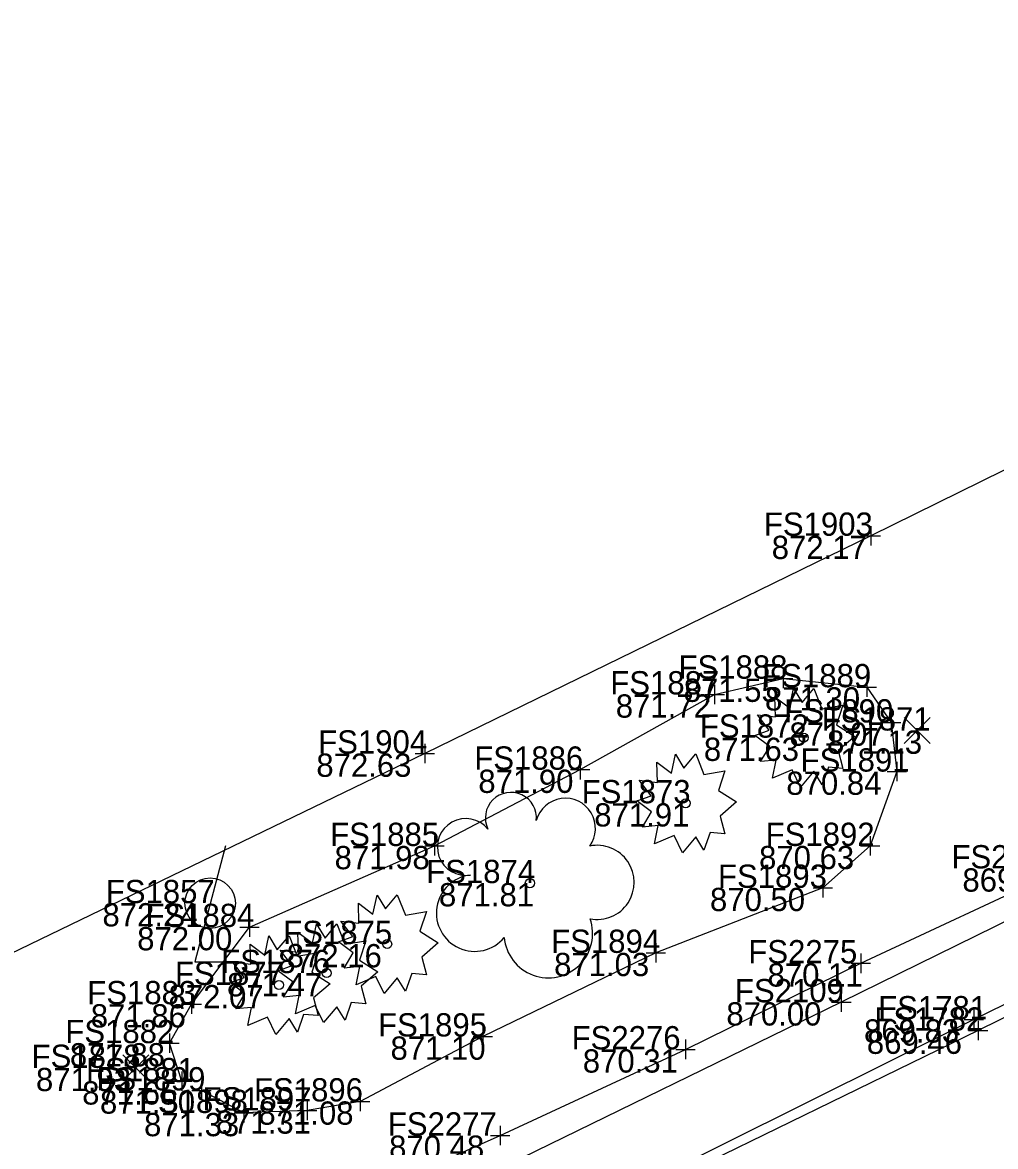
# Model space of a CAD drawing. Extents: x 1479420 to 1479833, y 379731 to 380103.
# Drawn here: x 1479688.8 to 1479739, y 379970.7 to 380028.7 of the extents above; entities that cross this region are included whole.
import ezdxf

# ---------------------------------------------------------------- set-up
doc = ezdxf.new("R2010")
doc.units = 0
for name, color, linetype in [('LT_X_Poles', 7, 'Continuous'), ('PV_X_Curb', 7, 'Continuous'), ('PV_X_Walk', 7, 'Continuous'), ('SV_X_Random_Point', 7, 'Continuous'), ('SV_X_Shot_Marker', 7, 'Continuous'), ('SV_X_Text_Elevation', 7, 'Continuous'), ('SV_X_Text_Name', 7, 'Continuous'), ('UT_X_Gas', 7, 'Continuous'), ('VG_X_Cells', 7, 'Continuous'), ('VG_X_Flower_Bed', 7, 'Continuous')]:
    doc.layers.add(name, color=color, linetype=linetype)

msp = doc.modelspace()

# ---------------------------------------------------------------- linework, layer by layer
at = {"layer": 'LT_X_Poles'}
msp.add_lwpolyline([(1479699.283, 379986.176), (1479697.708, 379980.191), (1479700.071, 379980.191)], dxfattribs=at)
msp.add_circle((1479698.496, 379983.222), 1.3, dxfattribs=at)
at = {"layer": 'PV_X_Curb'}
for points in [[(1479795.994, 380033.189), (1479773.609, 380022.189), (1479753.08, 380012.28), (1479732.582, 380002.187), (1479709.578, 379990.944), (1479686.038, 379979.568), (1479675.424, 379995.638), (1479673.845, 379997.042), (1479672.388, 379997.402), (1479671.072, 379997.477), (1479668.749, 379997.507), (1479666.577, 379997.444), (1479665.261, 379997.435), (1479663.761, 379996.907), (1479662.621, 379996.118), (1479646.813, 379979.589), (1479631.39, 379994.413), (1479612.948, 380012.393), (1479594.615, 380030.048), (1479574.047, 380049.976), (1479559.355, 380064.639), (1479550.33, 380073.358), (1479530.481, 380092.839), (1479523.351, 380099.687)], [(1479791.59, 380003.464), (1479772.982, 379994.381), (1479762.438, 379989.23), (1479737.891, 379977.225), (1479720.638, 379968.611), (1479698.71, 379957.883), (1479678.409, 379947.915), (1479674.816, 379946.157), (1479670.835, 379944.353), (1479668.74, 379943.532), (1479666.343, 379942.649), (1479664.179, 379942.195), (1479661.876, 379941.9), (1479659.999, 379941.971), (1479653.935, 379943.268), (1479649.182, 379945.527), (1479644.261, 379948.889), (1479643.432, 379949.993), (1479639.011, 379953.958), (1479638.818, 379953.848), (1479620.557, 379971.482), (1479582.44, 380008.391)], [(1479791.848, 380002.989), (1479773.254, 379993.873), (1479762.766, 379988.772), (1479738.122, 379976.643), (1479720.845, 379968.214), (1479698.694, 379957.239), (1479678.815, 379947.539), (1479674.951, 379945.56), (1479671.194, 379943.855), (1479668.836, 379942.929), (1479666.481, 379942.243), (1479664.295, 379941.704), (1479662.026, 379941.397), (1479659.994, 379941.512), (1479654.023, 379942.767), (1479648.758, 379945.101), (1479643.81, 379948.553), (1479642.638, 379949.516), (1479640.65, 379951.389), (1479638.379, 379953.495), (1479620.029, 379971.274), (1479601.931, 379988.801), (1479602.178, 379989.373), (1479582.142, 380008.015)]]:
    msp.add_lwpolyline(points, dxfattribs=at)
at = {"layer": 'PV_X_Walk'}
msp.add_lwpolyline([(1479748.905, 379986.887), (1479731.061, 379978.105), (1479713.158, 379969.376), (1479697.028, 379961.469), (1479684.159, 379955.33)], dxfattribs=at)
at = {"layer": 'SV_X_Random_Point'}
for p, q in [((1479734.312, 379991.465), (1479735.646, 379992.8)), ((1479734.312, 379992.8), (1479735.646, 379991.465)), ((1479693.992, 379974.051), (1479695.326, 379975.386)), ((1479693.992, 379975.386), (1479695.326, 379974.051))]:
    msp.add_line(p, q, dxfattribs=at)
at = {"layer": 'SV_X_Shot_Marker'}
for p, q in [((1479732.582, 380002.687), (1479732.582, 380001.687)), ((1479732.082, 380002.187), (1479733.082, 380002.187)), ((1479732.582, 380002.187), (1479732.582, 380002.187)), ((1479728.055, 379995.312), (1479728.055, 379994.312)), ((1479732.376, 379994.868), (1479732.376, 379993.868)), ((1479724.526, 379994.498), (1479724.526, 379993.498)), ((1479727.555, 379994.812), (1479728.555, 379994.812)), ((1479728.055, 379994.812), (1479728.055, 379994.812)), ((1479731.876, 379994.368), (1479732.876, 379994.368)), ((1479732.376, 379994.368), (1479732.376, 379994.368)), ((1479724.026, 379993.998), (1479725.026, 379993.998)), ((1479724.526, 379993.998), (1479724.526, 379993.998)), ((1479733.126, 379992.55), (1479734.126, 379992.55)), ((1479733.626, 379993.05), (1479733.626, 379992.05)), ((1479733.626, 379992.55), (1479733.626, 379992.55)), ((1479709.578, 379991.444), (1479709.578, 379990.444)), ((1479709.078, 379990.944), (1479710.078, 379990.944)), ((1479709.578, 379990.944), (1479709.578, 379990.944)), ((1479717.585, 379990.613), (1479717.585, 379989.613)), ((1479733.93, 379990.514), (1479733.93, 379989.514)), ((1479717.085, 379990.113), (1479718.085, 379990.113)), ((1479717.585, 379990.113), (1479717.585, 379990.113)), ((1479733.43, 379990.014), (1479734.43, 379990.014)), ((1479733.93, 379990.014), (1479733.93, 379990.014)), ((1479709.574, 379986.174), (1479710.574, 379986.174)), ((1479710.074, 379986.674), (1479710.074, 379985.674)), ((1479710.074, 379986.174), (1479710.074, 379986.174)), ((1479732.052, 379986.177), (1479733.052, 379986.177)), ((1479732.552, 379986.677), (1479732.552, 379985.677)), ((1479732.552, 379986.177), (1479732.552, 379986.177)), ((1479730.104, 379984.513), (1479730.104, 379983.513)), ((1479729.604, 379984.013), (1479730.604, 379984.013)), ((1479730.104, 379984.013), (1479730.104, 379984.013)), ((1479700.533, 379982.489), (1479700.533, 379981.489)), ((1479700.033, 379981.989), (1479701.033, 379981.989)), ((1479700.533, 379981.989), (1479700.533, 379981.989)), ((1479721.485, 379981.156), (1479721.485, 379980.156)), ((1479720.985, 379980.656), (1479721.985, 379980.656)), ((1479721.485, 379980.656), (1479721.485, 379980.656)), ((1479732.065, 379980.616), (1479732.065, 379979.616)), ((1479731.565, 379980.116), (1479732.565, 379980.116)), ((1479732.065, 379980.116), (1479732.065, 379980.116)), ((1479731.061, 379978.605), (1479731.061, 379977.605)), ((1479697.542, 379978.505), (1479697.542, 379977.505)), ((1479730.561, 379978.105), (1479731.561, 379978.105)), ((1479731.061, 379978.105), (1479731.061, 379978.105)), ((1479697.042, 379978.005), (1479698.042, 379978.005)), ((1479697.542, 379978.005), (1479697.542, 379978.005)), ((1479737.891, 379977.725), (1479737.891, 379976.725)), ((1479737.391, 379977.225), (1479738.391, 379977.225)), ((1479737.891, 379977.225), (1479737.891, 379977.225)), ((1479738.122, 379977.143), (1479738.122, 379976.143)), ((1479696.399, 379976.495), (1479696.399, 379975.495)), ((1479712.063, 379976.34), (1479713.063, 379976.34)), ((1479712.563, 379976.84), (1479712.563, 379975.84)), ((1479712.563, 379976.34), (1479712.563, 379976.34)), ((1479737.622, 379976.643), (1479738.622, 379976.643)), ((1479738.122, 379976.643), (1479738.122, 379976.643)), ((1479695.899, 379975.995), (1479696.899, 379975.995)), ((1479696.399, 379975.995), (1479696.399, 379975.995)), ((1479723.024, 379976.176), (1479723.024, 379975.176)), ((1479722.524, 379975.676), (1479723.524, 379975.676)), ((1479723.024, 379975.676), (1479723.024, 379975.676)), ((1479696.543, 379974.026), (1479697.543, 379974.026)), ((1479697.043, 379974.526), (1479697.043, 379973.526)), ((1479697.043, 379974.026), (1479697.043, 379974.026)), ((1479698.045, 379974.057), (1479698.045, 379973.057)), ((1479697.545, 379973.557), (1479698.545, 379973.557)), ((1479698.045, 379973.557), (1479698.045, 379973.557)), ((1479706.239, 379973.487), (1479706.239, 379972.487)), ((1479700.236, 379972.892), (1479700.236, 379971.892)), ((1479703.506, 379973.023), (1479703.506, 379972.023)), ((1479705.739, 379972.987), (1479706.739, 379972.987)), ((1479706.239, 379972.987), (1479706.239, 379972.987)), ((1479699.736, 379972.392), (1479700.736, 379972.392)), ((1479700.236, 379972.392), (1479700.236, 379972.392)), ((1479703.006, 379972.523), (1479704.006, 379972.523)), ((1479703.506, 379972.523), (1479703.506, 379972.523)), ((1479713.465, 379971.726), (1479713.465, 379970.726)), ((1479712.965, 379971.226), (1479713.965, 379971.226)), ((1479713.465, 379971.226), (1479713.465, 379971.226))]:
    msp.add_line(p, q, dxfattribs=at)
at = {"layer": 'UT_X_Gas'}
msp.add_lwpolyline([(1479590.076, 380006.869), (1479598.835, 379999.983), (1479606.591, 379993.985), (1479615.604, 379985.249), (1479623.747, 379977.629), (1479632.184, 379969.538), (1479638.836, 379962.809), (1479646.785, 379955.438), (1479652.981, 379949.433), (1479657.465, 379945.964), (1479660.591, 379945.024), (1479670.935, 379949.08), (1479679.157, 379953.065), (1479685.442, 379955.742), (1479689.462, 379958.127), (1479696.956, 379963.013), (1479705.088, 379967.488), (1479713.465, 379971.226), (1479723.024, 379975.676), (1479732.065, 379980.116), (1479742.535, 379985.018)], dxfattribs=at)
at = {"layer": 'VG_X_Cells'}
for points in [[(1479729.034, 379993.575), (1479729.639, 379994.31), (1479730.054, 379993.256), (1479731.146, 379993.436), (1479730.807, 379992.425), (1479731.752, 379991.83), (1479730.896, 379991.095), (1479731.146, 379990.181), (1479730.392, 379990.25), (1479730.067, 379989.336), (1479729.639, 379990.028), (1479728.961, 379989.211), (1479728.532, 379990.098), (1479727.512, 379989.668), (1479727.704, 379990.61), (1479726.892, 379990.526), (1479727.366, 379991.316), (1479726.597, 379991.885), (1479727.336, 379992.148), (1479726.729, 379992.951), (1479727.661, 379992.841), (1479727.631, 379993.88), (1479728.384, 379993.311), (1479728.591, 379994.296), (1479729.034, 379993.575)], [(1479722.943, 379990.189), (1479723.548, 379990.924), (1479723.963, 379989.87), (1479725.055, 379990.05), (1479724.716, 379989.039), (1479725.661, 379988.444), (1479724.805, 379987.709), (1479725.055, 379986.795), (1479724.301, 379986.864), (1479723.976, 379985.95), (1479723.548, 379986.642), (1479722.87, 379985.825), (1479722.441, 379986.712), (1479721.421, 379986.282), (1479721.613, 379987.224), (1479720.801, 379987.14), (1479721.275, 379987.93), (1479720.506, 379988.499), (1479721.245, 379988.762), (1479720.638, 379989.565), (1479721.57, 379989.455), (1479721.54, 379990.494), (1479722.293, 379989.925), (1479722.5, 379990.91), (1479722.943, 379990.189)], [(1479707.548, 379982.921), (1479708.153, 379983.656), (1479708.568, 379982.603), (1479709.66, 379982.783), (1479709.321, 379981.771), (1479710.266, 379981.176), (1479709.41, 379980.441), (1479709.66, 379979.528), (1479708.906, 379979.596), (1479708.581, 379978.683), (1479708.153, 379979.374), (1479707.475, 379978.558), (1479707.046, 379979.444), (1479706.026, 379979.014), (1479706.218, 379979.956), (1479705.406, 379979.873), (1479705.88, 379980.663), (1479705.111, 379981.231), (1479705.85, 379981.494), (1479705.243, 379982.298), (1479706.175, 379982.188), (1479706.145, 379983.226), (1479706.898, 379982.658), (1479707.105, 379983.643), (1479707.548, 379982.921)], [(1479704.422, 379981.423), (1479705.027, 379982.158), (1479705.442, 379981.104), (1479706.534, 379981.284), (1479706.195, 379980.273), (1479707.14, 379979.678), (1479706.284, 379978.943), (1479706.534, 379978.029), (1479705.78, 379978.098), (1479705.455, 379977.184), (1479705.027, 379977.876), (1479704.349, 379977.059), (1479703.92, 379977.946), (1479702.9, 379977.516), (1479703.092, 379978.458), (1479702.28, 379978.374), (1479702.754, 379979.164), (1479701.985, 379979.733), (1479702.724, 379979.996), (1479702.117, 379980.799), (1479703.049, 379980.689), (1479703.019, 379981.728), (1479703.772, 379981.159), (1479703.979, 379982.144), (1479704.422, 379981.423)], [(1479701.962, 379980.808), (1479702.567, 379981.543), (1479702.982, 379980.49), (1479704.074, 379980.67), (1479703.735, 379979.658), (1479704.68, 379979.063), (1479703.824, 379978.328), (1479704.074, 379977.415), (1479703.32, 379977.483), (1479702.995, 379976.57), (1479702.567, 379977.262), (1479701.889, 379976.445), (1479701.46, 379977.332), (1479700.44, 379976.902), (1479700.632, 379977.843), (1479699.82, 379977.76), (1479700.294, 379978.55), (1479699.525, 379979.118), (1479700.264, 379979.382), (1479699.657, 379980.185), (1479700.589, 379980.075), (1479700.559, 379981.113), (1479701.312, 379980.545), (1479701.519, 379981.53), (1479701.962, 379980.808)]]:
    msp.add_lwpolyline(points, dxfattribs=at)
for centre, radius in [((1479729.118, 379991.765), 0.23), ((1479723.027, 379988.379), 0.23), ((1479714.998, 379984.257), 0.24), ((1479707.632, 379981.111), 0.23), ((1479704.506, 379979.613), 0.23), ((1479702.046, 379978.999), 0.23)]:
    msp.add_circle(centre, radius, dxfattribs=at)
for centre, radius, start, end in [((1479714.014, 379987.625), 1.317, 354.0047, 205.97412), ((1479716.824, 379987.086), 1.553, 323.82996, 165.0376), ((1479711.689, 379986.121), 1.471, 39.06254, 279.54124), ((1479718.458, 379984.293), 1.915, 259.14531, 101.45961), ((1479712.145, 379982.708), 1.974, 96.17219, 320.57371), ((1479715.944, 379981.652), 2.284, 184.94757, 19.45715)]:
    msp.add_arc(centre, radius, start, end, dxfattribs=at)
at = {"layer": 'VG_X_Flower_Bed'}
msp.add_lwpolyline([(1479697.043, 379974.026), (1479696.399, 379975.995), (1479697.542, 379978.005), (1479700.533, 379981.989), (1479710.074, 379986.174), (1479717.585, 379990.113), (1479724.526, 379993.998), (1479728.055, 379994.812), (1479732.376, 379994.368), (1479733.626, 379992.55), (1479733.93, 379990.014), (1479732.552, 379986.177), (1479730.104, 379984.013), (1479721.485, 379980.656), (1479712.563, 379976.34), (1479706.239, 379972.987), (1479703.506, 379972.523), (1479700.236, 379972.392), (1479698.045, 379973.557)], dxfattribs=at)

# ---------------------------------------------------------------- texts
at = {"layer": 'SV_X_Text_Elevation'}
for s, p in [('872.17', (1479727.471, 380000.987)), ('871.55', (1479722.925, 379993.612)), ('871.30', (1479727.123, 379993.168)), ('871.72', (1479719.425, 379992.798)), ('871.07', (1479728.383, 379991.35)), ('871.13', (1479730.322, 379990.933)), ('871.63', (1479723.97, 379990.565)), ('872.63', (1479703.975, 379989.744)), ('871.90', (1479712.332, 379988.913)), ('870.84', (1479728.223, 379988.814)), ('871.91', (1479718.313, 379987.179)), ('871.98', (1479704.916, 379984.974)), ('870.63', (1479726.817, 379984.977)), ('869.81', (1479737.309, 379983.818)), ('871.81', (1479710.302, 379983.057)), ('870.50', (1479724.284, 379982.813)), ('872.24', (1479692.94, 379982.022)), ('872.00', (1479694.732, 379980.789)), ('872.16', (1479702.447, 379979.911)), ('871.03', (1479716.242, 379979.456)), ('870.11', (1479727.256, 379978.916)), ('871.47', (1479699.368, 379978.413)), ('872.07', (1479696.35, 379977.798)), ('871.86', (1479692.337, 379976.805)), ('870.00', (1479725.128, 379976.905)), ('869.83', (1479732.232, 379976.025)), ('871.10', (1479707.802, 379975.14)), ('869.46', (1479732.378, 379975.443)), ('871.88', (1479691.26, 379974.795)), ('870.31', (1479717.723, 379974.476)), ('871.93', (1479689.51, 379973.519)), ('871.65', (1479691.894, 379972.826)), ('871.50', (1479692.811, 379972.357)), ('871.08', (1479700.986, 379971.787)), ('871.33', (1479695.087, 379971.192)), ('871.31', (1479698.791, 379971.323)), ('870.48', (1479707.73, 379970.026))]:
    msp.add_text(s, height=1.2, dxfattribs=at).set_placement(p)
at = {"layer": 'SV_X_Text_Name'}
for s, p in [('FS1903', (1479727.065, 380002.187)), ('FS1888', (1479722.661, 379994.812)), ('FS1889', (1479726.982, 379994.368)), ('FS1887', (1479719.141, 379993.998)), ('FS1890', (1479728.118, 379992.55)), ('FS1871', (1479730.047, 379992.133)), ('FS1872', (1479723.763, 379991.765)), ('FS1904', (1479704.07, 379990.944)), ('FS1886', (1479712.125, 379990.113)), ('FS1891', (1479728.96, 379990.014)), ('FS1873', (1479717.662, 379988.379)), ('FS1885', (1479704.689, 379986.174)), ('FS1892', (1479727.158, 379986.177)), ('FS2274', (1479736.743, 379985.018)), ('FS1874', (1479709.642, 379984.257)), ('FS1893', (1479724.7, 379984.013)), ('FS1857', (1479693.111, 379983.222)), ('FS1884', (1479695.158, 379981.989)), ('FS1875', (1479702.267, 379981.111)), ('FS1894', (1479716.091, 379980.656)), ('FS2275', (1479726.264, 379980.116)), ('FS1876', (1479699.066, 379979.613)), ('FS1877', (1479696.681, 379978.998)), ('FS1883', (1479692.157, 379978.005)), ('FS2109', (1479725.572, 379978.105)), ('FS1781', (1479732.959, 379977.225)), ('FS1895', (1479707.159, 379976.34)), ('FS1782', (1479732.766, 379976.643)), ('FS1882', (1479691.024, 379975.995)), ('FS2276', (1479717.147, 379975.676)), ('FS1878', (1479689.284, 379974.719)), ('FS1881', (1479692.092, 379974.026)), ('FS1899', (1479692.632, 379973.557)), ('FS1896', (1479700.76, 379972.987)), ('FS1898', (1479694.823, 379972.392)), ('FS1897', (1479698.102, 379972.523)), ('FS2277', (1479707.664, 379971.226))]:
    msp.add_text(s, height=1.2, dxfattribs=at).set_placement(p)

doc.saveas('drawing.dxf')
